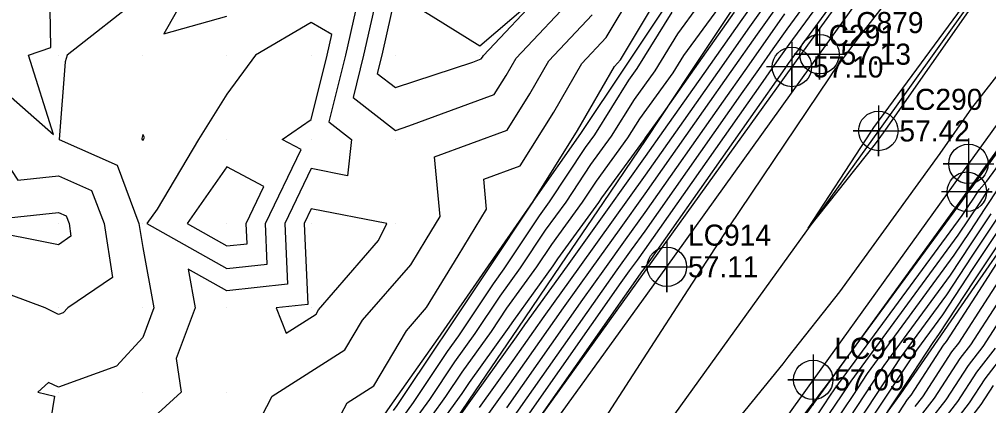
# Model space of a CAD drawing. Extents: x 2188792 to 2191981, y 386090 to 389710.
# Drawn here: x 2189815.5 to 2189930.5, y 387278.5 to 387324.4 of the extents above; entities that cross this region are included whole.
import ezdxf

# ---------------------------------------------------------------- set-up
doc = ezdxf.new("R2010")
doc.units = 0
for name, color, linetype in [('DTM Contours Major', 7, 'Continuous'), ('DTM Contours Minor', 7, 'Continuous'), ('Exist DTM QL2 LIDAR Elevation Point', 7, 'Continuous'), ('Exist Roads EOP', 7, 'Continuous'), ('Exist Roads EOP Cogo Elevation', 7, 'Continuous'), ('Exist Roads EOP Cogo Number', 7, 'Continuous'), ('Exist Roads EOP Cogo Point CELL', 7, 'Continuous'), ('Exist Roads EOT', 7, 'Continuous'), ('Exist Roads EOT Cogo Elevation', 7, 'Continuous'), ('Exist Roads EOT Cogo Number', 7, 'Continuous'), ('Exist Roads EOT Cogo Point CELL', 7, 'Continuous'), ('PH Exist DTM Breakline', 7, 'Continuous')]:
    doc.layers.add(name, color=color, linetype=linetype)

msp = doc.modelspace()

# ---------------------------------------------------------------- linework, layer by layer
at = {"layer": 'DTM Contours Major'}
for points in [[(2189839.48, 387181.41), (2189856.6, 387205.43), (2189856.62, 387205.47), (2189856.64, 387205.5), (2189856.66, 387205.52), (2189858.22, 387207.73), (2189869.83, 387224.62), (2189877.25, 387235.16), (2189886.02, 387247.79), (2189890.66, 387253.9), (2189892.44, 387256.25), (2189909.42, 387278.54), (2189910.29, 387279.68), (2189910.31, 387279.71), (2189911.35, 387281.07), (2189927.82, 387303.46), (2189927.93, 387303.63), (2189928.04, 387303.8), (2189928.15, 387303.96), (2189928.3, 387304.13), (2189939.5, 387319.43), (2189939.71, 387319.86), (2189939.83, 387320.31), (2189949.95, 387334.28)], [(2189918.14, 387334.76), (2189907.02, 387319.58), (2189906.71, 387319.13), (2189906.37, 387318.66), (2189906.02, 387318.16), (2189889.61, 387294.83), (2189889.46, 387294.62), (2189889.3, 387294.4), (2189889.13, 387294.16), (2189875.84, 387275.24)], [(2189870.05, 387278.3), (2189874.07, 387283.9), (2189877.74, 387289.12), (2189881.96, 387295), (2189885.96, 387300.58), (2189889.75, 387305.88), (2189894.3, 387312.33), (2189898.34, 387318.06), (2189902.16, 387323.49), (2189905.78, 387328.63)], [(2189860.09, 387327.41), (2189858.46, 387320.14), (2189857.91, 387317.96), (2189860.09, 387316.28), (2189869.27, 387319.31), (2189870.26, 387319.67), (2189870.4, 387319.9), (2189870.52, 387320.1), (2189877.68, 387327.72), (2189870.1, 387321.18), (2189864.57, 387324.61), (2189860.09, 387327.41)], [(2189860.8, 387276.95), (2189862.22, 387278.92), (2189866.25, 387284.95), (2189867.61, 387286.84), (2189871.71, 387292.99), (2189873, 387294.77), (2189877.17, 387301.05), (2189878.38, 387302.72), (2189882.65, 387309.15), (2189883.77, 387310.68), (2189887.79, 387317.14), (2189888.78, 387318.52), (2189892.93, 387325.24)], [(2189799.94, 387300.13), (2189800.09, 387300.51), (2189800.77, 387300.82), (2189810.09, 387300.9), (2189810.39, 387300.44), (2189820.09, 387301.46), (2189821.01, 387301.05), (2189821.35, 387300.13), (2189821.58, 387298.64), (2189820.09, 387297.62), (2189810.73, 387299.49), (2189810.09, 387299.73), (2189809.64, 387299.69), (2189800.09, 387299.74), (2189799.94, 387300.13)], [(2189931.41, 387300.66), (2189928.51, 387296.27), (2189925.47, 387291.68), (2189919.98, 387284.21), (2189917.13, 387279.86), (2189913.61, 387274.54)], [(2189931.48, 387290.59), (2189928.35, 387285.76), (2189927.08, 387284.12), (2189924.02, 387279.41), (2189922.66, 387277.66)]]:
    msp.add_lwpolyline(points, dxfattribs=at)
at = {"layer": 'DTM Contours Minor'}
for points in [[(2189946.66, 387352.03), (2189946.76, 387352.15), (2189946.69, 387352.01), (2189946.66, 387351.98), (2189929.64, 387327.53), (2189929.17, 387326.93), (2189917.99, 387310.91), (2189917.03, 387309.59), (2189909.09, 387299.59), (2189915.98, 387310.21), (2189916.94, 387311.64), (2189916.97, 387311.69), (2189928.49, 387327.34), (2189929.16, 387328.21), (2189946.64, 387352.01), (2189946.66, 387352.03)], [(2189806.1, 387171.08), (2189818.83, 387185.77), (2189823.98, 387192.84), (2189832.15, 387202.52), (2189840.64, 387214.2), (2189849.54, 387226.21), (2189857.02, 387236.63), (2189863.86, 387245.87), (2189872.91, 387258.47), (2189874.44, 387260.83), (2189883.3, 387274.48), (2189889.96, 387284.76), (2189894.84, 387292.27), (2189899.7, 387299.76), (2189911.6, 387317.43), (2189912.05, 387318.1), (2189914.93, 387322.01), (2189928.34, 387339.25)], [(2189916.42, 387334.55), (2189906.77, 387321.39), (2189905.8, 387320), (2189904.77, 387318.54), (2189903.68, 387317), (2189889.64, 387297.04), (2189888.76, 387295.81), (2189887.83, 387294.52), (2189886.85, 387293.15), (2189872.46, 387272.67)], [(2189914.69, 387334.35), (2189906.53, 387323.2), (2189904.89, 387320.87), (2189903.16, 387318.42), (2189901.33, 387315.83), (2189889.67, 387299.25), (2189888.06, 387297.01), (2189886.37, 387294.64), (2189884.58, 387292.14), (2189872.86, 387275.48)], [(2189864.51, 387272.83), (2189869.64, 387279.97), (2189874.47, 387286.7), (2189875.46, 387288.11), (2189880.49, 387295.13), (2189885.26, 387301.77), (2189889.78, 387308.09), (2189891.95, 387311.17), (2189896.73, 387317.95), (2189901.25, 387324.36), (2189905.54, 387330.44)], [(2189810.09, 387318.97), (2189819.5, 387310.72), (2189816.55, 387320.14), (2189819.2, 387321.03), (2189819.01, 387330.14)], [(2189836.83, 387330.14), (2189832.59, 387322.64), (2189840.09, 387324.76)], [(2189858.11, 387328.15), (2189856.3, 387320.14), (2189855.05, 387315.09), (2189860.09, 387311.2), (2189861.69, 387311.73), (2189871.81, 387315.44), (2189873.22, 387317.71), (2189874.41, 387319.77), (2189881.73, 387327.56)], [(2189830.09, 387327.2), (2189821.12, 387320.14), (2189820.9, 387319.32), (2189820.19, 387310.13), (2189827.04, 387307.08), (2189829.65, 387300.13), (2189830.09, 387297.29), (2189831.41, 387290.13), (2189830.09, 387286.61), (2189826.98, 387283.24), (2189820.09, 387280.72), (2189818.92, 387281.3), (2189817.63, 387280.13), (2189819.64, 387279.68), (2189818.08, 387270.13), (2189810.09, 387261.58)], [(2189813.86, 387243.81), (2189820.22, 387242.11), (2189828.74, 387243.3), (2189831.38, 387248.15), (2189833.99, 387252.94), (2189837.73, 387256.94), (2189841.91, 387259.44), (2189846.25, 387264.44), (2189851.31, 387270.28), (2189850.9, 387272.4), (2189854.35, 387278.87), (2189857.51, 387280.88), (2189861.39, 387287.42), (2189863.78, 387290.18), (2189867.52, 387296.31), (2189870.9, 387301.85), (2189870.57, 387305.4), (2189874.9, 387306.99), (2189878.87, 387313.35), (2189882.19, 387319.12), (2189885.11, 387322.22), (2189888.38, 387327.73)], [(2189859.87, 387277.98), (2189860.3, 387278.57), (2189865.38, 387286.18), (2189865.68, 387286.59), (2189870.9, 387294.43), (2189871.06, 387294.65), (2189876.25, 387302.46), (2189876.42, 387302.73), (2189876.42, 387302.75), (2189876.44, 387302.76), (2189881.69, 387311.17), (2189886.08, 387318.79), (2189886.79, 387319.55), (2189891.18, 387326.92)], [(2189937.84, 387325.8), (2189928.45, 387313.82), (2189924.71, 387308.45), (2189912.79, 387292.05), (2189906.64, 387284.3), (2189906.06, 387283.51), (2189895.67, 387270.72), (2189887.11, 387259.92), (2189885.22, 387257.52), (2189881.38, 387252.79), (2189871.55, 387239.19), (2189863.95, 387228.23), (2189855.91, 387217.12), (2189849.6, 387208.01), (2189840.53, 387195.39), (2189832.22, 387183.39), (2189825.82, 387174.47), (2189818.87, 387164.42), (2189809.4, 387152.41)], [(2189861.73, 387275.92), (2189864.15, 387279.28), (2189867.12, 387283.73), (2189869.54, 387287.09), (2189872.51, 387291.54), (2189874.94, 387294.89), (2189877.9, 387299.35), (2189880.33, 387302.7), (2189883.29, 387307.16), (2189885.73, 387310.5), (2189888.44, 387314.86), (2189890.92, 387318.27), (2189893.62, 387322.66), (2189896.11, 387326.05)], [(2189862.65, 387274.88), (2189866.07, 387279.64), (2189867.99, 387282.5), (2189871.47, 387287.33), (2189873.31, 387290.09), (2189876.88, 387295.02), (2189878.63, 387297.65), (2189882.28, 387302.67), (2189883.93, 387305.17), (2189887.68, 387310.31), (2189889.1, 387312.58), (2189893.05, 387318.03), (2189894.32, 387320.08), (2189898.47, 387325.73)], [(2189870.46, 387276.62), (2189873.67, 387281.09), (2189880.02, 387290.13), (2189883.43, 387294.88), (2189886.66, 387299.39), (2189889.73, 387303.67), (2189896.64, 387313.5), (2189899.94, 387318.18), (2189903.07, 387322.62), (2189906.03, 387326.82)], [(2189810.44, 387250.13), (2189816.94, 387246.94), (2189820.15, 387246.08), (2189824.46, 387246.68), (2189825.79, 387249.13), (2189830.94, 387258.57), (2189831.75, 387259.44), (2189840.97, 387264.95), (2189843.08, 387267.37), (2189845.53, 387270.2), (2189844.17, 387277.22), (2189845.47, 387279.66), (2189854.09, 387285.15), (2189856.18, 387288.67), (2189861.9, 387295.26), (2189863.73, 387298.26), (2189865.38, 387300.97), (2189864.71, 387308.04), (2189873.35, 387311.22), (2189876.04, 387315.53), (2189878.3, 387319.44), (2189883.42, 387324.89)], [(2189855.33, 387325.37), (2189854.15, 387320.14), (2189852.18, 387312.22), (2189854.89, 387310.13), (2189854.41, 387305.81), (2189850.09, 387306.67), (2189846.95, 387300.13), (2189847.29, 387292.94), (2189840.09, 387292.17), (2189835.48, 387294.74), (2189836.33, 387290.13), (2189834.08, 387284.12), (2189834.65, 387280.13), (2189830.09, 387275.99), (2189824.77, 387270.13), (2189827.04, 387263.18), (2189824.07, 387260.13), (2189820.09, 387258.6), (2189814.34, 387255.88)], [(2189863.58, 387273.85), (2189868, 387279.99), (2189868.86, 387281.28), (2189873.4, 387287.58), (2189874.12, 387288.65), (2189878.81, 387295.14), (2189879.36, 387295.96), (2189884.22, 387302.65), (2189884.57, 387303.18), (2189889.64, 387310.12), (2189889.75, 387310.3), (2189891.92, 387313.29), (2189895.12, 387317.83), (2189900.34, 387325.23)], [(2189906.28, 387325.01), (2189903.98, 387321.75), (2189901.55, 387318.3), (2189898.99, 387314.66), (2189889.7, 387301.46), (2189887.36, 387298.2), (2189884.9, 387294.76), (2189882.3, 387291.14), (2189873.26, 387278.28)], [(2189851.99, 387320.14), (2189852.55, 387322.59), (2189850.09, 387324), (2189843.46, 387320.14), (2189840.09, 387315.5), (2189836.71, 387310.13), (2189831.8, 387301.84), (2189830.6, 387300.13), (2189840.09, 387294.83), (2189844.88, 387295.34), (2189844.66, 387300.13), (2189848.89, 387308.94), (2189846.65, 387310.13), (2189850.09, 387312.49), (2189851.99, 387320.14)], [(2189910.18, 387277.45), (2189910.96, 387278.62), (2189911.66, 387279.67), (2189912.22, 387280.53), (2189927.35, 387301.1), (2189928.05, 387302.16), (2189928.72, 387303.17), (2189929.36, 387304.14), (2189930.29, 387305.19), (2189939.71, 387318.06)], [(2189797.34, 387300.13), (2189800.09, 387307.38), (2189806.28, 387310.13), (2189810.09, 387311.88), (2189812.08, 387310.13), (2189815.27, 387305.31), (2189820.09, 387305.82), (2189824.02, 387304.07), (2189825.5, 387300.13), (2189826.5, 387293.73), (2189821.2, 387290.13), (2189820.67, 387289.56), (2189820.09, 387289.35), (2189818.5, 387290.13), (2189810.09, 387293.26), (2189802.48, 387292.53), (2189800.09, 387292.54), (2189797.34, 387300.13)], [(2189830.09, 387310.7), (2189829.98, 387310.25), (2189829.97, 387310.13), (2189830.05, 387310.1), (2189830.09, 387309.99), (2189830.17, 387310.13), (2189830.32, 387310.36), (2189830.09, 387310.7)], [(2189842.37, 387300.13), (2189844.48, 387304.52), (2189840.09, 387306.87), (2189835.36, 387300.13), (2189840.09, 387297.49), (2189842.48, 387297.74), (2189842.37, 387300.13)], [(2189849.09, 387187.08), (2189855.51, 387196.1), (2189858.56, 387200.61), (2189861.48, 387204.93), (2189864.28, 387209.08), (2189870.41, 387217.72), (2189872.92, 387221.8), (2189874.97, 387225.12), (2189876.67, 387227.86), (2189886.9, 387242.24), (2189888.82, 387245.23), (2189890.64, 387248.07), (2189892.22, 387250.53), (2189894.77, 387253.97), (2189896.25, 387256.26), (2189897.56, 387258.28), (2189910.06, 387275.24), (2189911.62, 387277.6), (2189913.03, 387279.72), (2189914.16, 387281.45), (2189926.88, 387298.75), (2189928.16, 387300.69), (2189929.39, 387302.54), (2189930.56, 387304.32)], [(2189854.97, 387191.43), (2189859.53, 387198.18), (2189863.9, 387204.65), (2189868.09, 387210.85), (2189869.87, 387213.36), (2189873.73, 387219.61), (2189876.86, 387224.69), (2189879.46, 387228.89), (2189885.68, 387237.63), (2189888.71, 387242.35), (2189891.58, 387246.83), (2189894.08, 387250.71), (2189895.92, 387253.21), (2189898.24, 387256.79), (2189900.28, 387259.94), (2189909.93, 387273.03), (2189912.28, 387276.58), (2189914.4, 387279.76), (2189916.1, 387282.37), (2189926.41, 387296.39), (2189928.28, 387299.22), (2189930.06, 387301.92), (2189931.77, 387304.5)], [(2189859.07, 387300.13), (2189850.09, 387301.9), (2189849.24, 387300.13), (2189849.69, 387290.54), (2189845.92, 387290.13), (2189847.1, 387287.14), (2189850.67, 387289.41), (2189850.97, 387289.92), (2189858.09, 387298.13), (2189859.07, 387300.13)], [(2189930.74, 387301.29), (2189928.39, 387297.74), (2189925.94, 387294.03), (2189918.04, 387283.29), (2189915.76, 387279.81), (2189912.95, 387275.56)], [(2189932.09, 387300.03), (2189928.63, 387294.8), (2189925.01, 387289.32), (2189921.92, 387285.13), (2189918.5, 387279.9), (2189914.27, 387273.52)], [(2189932.76, 387299.41), (2189928.74, 387293.33), (2189924.54, 387286.97), (2189923.86, 387286.05), (2189919.87, 387279.95), (2189918.45, 387277.81)], [(2189933.42, 387298.47), (2189929.37, 387292.21), (2189925.45, 387286.16), (2189925.11, 387285.73), (2189921.25, 387279.79), (2189920.83, 387279.25), (2189916.49, 387272.64)], [(2189934.07, 387297.03), (2189930.42, 387291.4), (2189926.9, 387285.96), (2189926.1, 387284.93), (2189922.63, 387279.6), (2189921.74, 387278.45)], [(2189932.53, 387289.77), (2189929.8, 387285.56), (2189928.06, 387283.32), (2189925.4, 387279.23), (2189923.57, 387276.87)], [(2189931.25, 387285.36), (2189929.05, 387282.52), (2189926.79, 387279.04), (2189924.49, 387276.08)], [(2189932.7, 387285.16), (2189930.03, 387281.72), (2189928.17, 387278.86), (2189925.4, 387275.29)], [(2189931.01, 387280.91), (2189929.56, 387278.67), (2189926.31, 387274.5)]]:
    msp.add_lwpolyline(points, dxfattribs=at)
at = {"layer": 'Exist DTM QL2 LIDAR Elevation Point'}
for p, q in [((2189820.09, 387320.14), (2189820.09, 387320.14)), ((2189830.09, 387320.14), (2189830.09, 387320.14)), ((2189840.09, 387320.14), (2189840.09, 387320.14)), ((2189850.09, 387320.14), (2189850.09, 387320.14)), ((2189860.09, 387320.14), (2189860.09, 387320.14)), ((2189870.1, 387320.14), (2189870.1, 387320.14)), ((2189820.09, 387310.13), (2189820.09, 387310.13)), ((2189830.09, 387310.13), (2189830.09, 387310.13)), ((2189840.09, 387310.13), (2189840.09, 387310.13)), ((2189850.09, 387310.13), (2189850.09, 387310.13)), ((2189860.09, 387310.13), (2189860.09, 387310.13)), ((2189820.09, 387300.13), (2189820.09, 387300.13)), ((2189830.09, 387300.13), (2189830.09, 387300.13)), ((2189840.09, 387300.13), (2189840.09, 387300.13)), ((2189850.09, 387300.13), (2189850.09, 387300.13)), ((2189860.09, 387300.13), (2189860.09, 387300.13)), ((2189820.09, 387290.13), (2189820.09, 387290.13)), ((2189830.09, 387290.13), (2189830.09, 387290.13)), ((2189840.09, 387290.13), (2189840.09, 387290.13)), ((2189850.09, 387290.13), (2189850.09, 387290.13)), ((2189820.09, 387280.13), (2189820.09, 387280.13)), ((2189830.09, 387280.13), (2189830.09, 387280.13)), ((2189840.09, 387280.13), (2189840.09, 387280.13))]:
    msp.add_line(p, q, dxfattribs=at)
at = {"layer": 'Exist Roads EOP'}
for points in [[(2190313.99, 387884.14), (2190285.55, 387843.64), (2190254.59, 387800.04), (2190225.16, 387759.32), (2190194.83, 387717.43), (2190164.29, 387675.1), (2190137.23, 387637.3), (2190105.1, 387592.77), (2190071.41, 387546.22), (2190039.3, 387501.57), (2190007.54, 387457.96), (2189976.84, 387415.41), (2189936.36, 387359.15), (2189907.14, 387318.72), (2189868.64, 387265.24), (2189836.43, 387220.46), (2189805.69, 387177.81), (2189775.59, 387135.96), (2189745.5, 387094.06), (2189715.5, 387052.25), (2189683.87, 387008.07), (2189653.22, 386965.87), (2189623.73, 386924.67)], [(2190335.13, 387868.99), (2190306.37, 387829.27), (2190274.58, 387784.92), (2190245.13, 387744.07), (2190214.55, 387701.74), (2190184.89, 387660.47), (2190157.49, 387622.2), (2190126.05, 387578.5), (2190091.22, 387530.57), (2190059.63, 387486.73), (2190026.93, 387441.78), (2189997.69, 387401.03), (2189957.02, 387344.15), (2189927.91, 387303.92), (2189889.01, 387250.22), (2189856.61, 387205.5), (2189825.68, 387162.61), (2189795.67, 387120.82), (2189765.96, 387079.62), (2189735, 387036.7), (2189703.85, 386993.36), (2189673.98, 386951.98), (2189643.25, 386909.43)]]:
    msp.add_lwpolyline(points, dxfattribs=at)
at = {"layer": 'Exist Roads EOP Cogo Point CELL'}
for points in [[(2189907.14, 387321.72), (2189907.14, 387315.72), (2189907.14, 387318.72), (2189910.14, 387318.72), (2189904.14, 387318.72)], [(2189927.91, 387306.92), (2189927.91, 387300.92), (2189927.91, 387303.92), (2189930.91, 387303.92), (2189924.91, 387303.92)]]:
    msp.add_lwpolyline(points, dxfattribs=at)
for centre in [(2189907.14, 387318.72), (2189927.91, 387303.92)]:
    msp.add_circle(centre, 2.34, dxfattribs=at)
at = {"layer": 'Exist Roads EOT'}
for points in [[(2190174.38, 387667.89), (2190147.47, 387630.5), (2190115.25, 387585.78), (2190081.2, 387538.23), (2190049.5, 387494.26), (2190017.54, 387450.18), (2189987.33, 387408.36), (2189946.67, 387352.02), (2189917.4, 387311.13), (2189878.96, 387257.77), (2189846.56, 387212.82), (2189815.84, 387170.31), (2189785.37, 387128.35), (2189755.72, 387086.92), (2189724.95, 387044.04), (2189693.73, 387000.8), (2189663.93, 386959.22), (2189633.42, 386917.2)], [(2189989.25, 387391.99), (2189958.58, 387349.45), (2189928.09, 387307.22), (2189909.67, 387281.6), (2189884.44, 387246.51), (2189852.91, 387202.77), (2189821.51, 387159.3), (2189790.01, 387115.85), (2189759.16, 387072.96), (2189728.25, 387029.91), (2189696.41, 386985.69), (2189665.45, 386942.74), (2189635.05, 386900.5)], [(2189619.9, 386917.17), (2189650.19, 386959.04), (2189680.96, 387001.73), (2189713.17, 387046.57), (2189739.87, 387083.88), (2189771.56, 387127.85), (2189803.19, 387171.31), (2189835.06, 387215.5), (2189866.48, 387259.2), (2189892.31, 387295.02), (2189910.41, 387320.24), (2189942.08, 387364.22)]]:
    msp.add_lwpolyline(points, dxfattribs=at)
at = {"layer": 'Exist Roads EOT Cogo Point CELL'}
for points in [[(2189910.41, 387323.24), (2189910.41, 387317.24), (2189910.41, 387320.24), (2189907.41, 387320.24), (2189913.41, 387320.24)], [(2189917.4, 387314.13), (2189917.4, 387308.13), (2189917.4, 387311.13), (2189914.4, 387311.13), (2189920.4, 387311.13)], [(2189928.09, 387310.22), (2189928.09, 387304.22), (2189928.09, 387307.22), (2189925.09, 387307.22), (2189931.09, 387307.22)], [(2189892.31, 387298.02), (2189892.31, 387292.02), (2189892.31, 387295.02), (2189889.31, 387295.02), (2189895.31, 387295.02)], [(2189909.67, 387284.6), (2189909.67, 387278.6), (2189909.67, 387281.6), (2189906.67, 387281.6), (2189912.67, 387281.6)]]:
    msp.add_lwpolyline(points, dxfattribs=at)
for centre in [(2189910.41, 387320.24), (2189917.4, 387311.13), (2189928.09, 387307.22), (2189892.31, 387295.02), (2189909.67, 387281.6)]:
    msp.add_circle(centre, 2.34, dxfattribs=at)
at = {"layer": 'PH Exist DTM Breakline'}
for points in [[(2189853.83, 387270.31), (2189859.48, 387278.42), (2189865.14, 387286.52), (2189870.79, 387294.63), (2189876.45, 387302.74), (2189882.1, 387310.84), (2189887.34, 387318.68), (2189892.59, 387326.52)], [(2189900.04, 387325.52), (2189894.92, 387317.81), (2189889.81, 387310.1), (2189884.75, 387302.65), (2189879.68, 387295.19), (2189874.62, 387287.74), (2189869.56, 387280.28), (2189864.5, 387272.83), (2189859.44, 387265.37)], [(2189944.5, 387320.04), (2189940.82, 387310.8), (2189937.58, 387305.36), (2189933.19, 387299.01), (2189928.8, 387292.66), (2189924.41, 387286.3), (2189920.02, 387279.95), (2189914.76, 387272.76), (2189909.51, 387265.56), (2189904.26, 387258.37), (2189899, 387251.17), (2189893.75, 387243.98), (2189888.49, 387236.78)]]:
    msp.add_lwpolyline(points, dxfattribs=at)

# ---------------------------------------------------------------- texts
at = {"layer": 'Exist Roads EOP Cogo Elevation'}
msp.add_text('57.10', height=2.5, dxfattribs=at).set_placement((2189909.64, 387317.47))
at = {"layer": 'Exist Roads EOP Cogo Number'}
msp.add_text('LC291', height=2.5, dxfattribs=at).set_placement((2189909.64, 387321.22))
at = {"layer": 'Exist Roads EOT Cogo Elevation'}
for s, p in [('57.13', (2189912.91, 387318.99)), ('57.42', (2189919.9, 387309.88)), ('57.11', (2189894.81, 387293.77)), ('57.09', (2189912.17, 387280.35))]:
    msp.add_text(s, height=2.5, dxfattribs=at).set_placement(p)
at = {"layer": 'Exist Roads EOT Cogo Number'}
for s, p in [('LC879', (2189912.91, 387322.74)), ('LC290', (2189919.9, 387313.63)), ('LC914', (2189894.81, 387297.52)), ('LC913', (2189912.17, 387284.1))]:
    msp.add_text(s, height=2.5, dxfattribs=at).set_placement(p)

doc.saveas('drawing.dxf')
